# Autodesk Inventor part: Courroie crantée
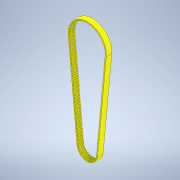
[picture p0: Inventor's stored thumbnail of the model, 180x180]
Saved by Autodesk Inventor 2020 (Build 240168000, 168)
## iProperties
Created: 2003-06
Part Number: Courroie crantée
Material: Générique
Document SubType Name: Modeling
Designer: Bruno
Density: 1 g/cm^3
Appearance: Par défaut
Author: Bruno
Sending System: SolidWorks 2011
Last Author: Professeur
Last Saved: 2014-11-10
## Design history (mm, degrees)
feature "Symétrie1"
node "Solide1"
